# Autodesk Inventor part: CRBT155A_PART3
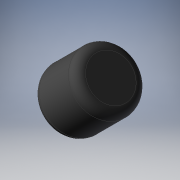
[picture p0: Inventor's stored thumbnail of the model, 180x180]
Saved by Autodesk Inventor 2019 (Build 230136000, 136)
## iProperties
Created: 2023-09
Part Number: CRBT155A_PART3
Material: Generic
Catalog Web Link: www.cadenas.de
Description: -
Vendor: IKO
Document SubType Name: Modeling
Designer: psAdmin
Manufacturer: IKO
Mass: 0.00605674 g
Surface Area: 0.171514 cm^2
Volume: 0.00605674 cm^3
Density: 1 g/cm^3
Appearance: PSOLRGB-192-192-192
Category: PARTsolutions
Company: IKO
Title: CRBT155A_PART3
Author: Cadenas PARTsolutions
PSOL_IDENT_0: {$CADENAS_DATA/23d-libs/iko/iko_bearings/crossed_rb/ultra_slim_type_crb/ultra_slim_type_crbt.prj},23
PSOL_IDENT_1: 2 {VTYP=3D},{NB=CRBT155A_PART3},{LINA=CRBT155A_PART3},{NN=Ultra Slim Type Crossed Roller Bearings (C
PSOL_IDENT_2: RBT...A)_PART3},{NOPRJ=TRUE},{DATE=09.07.2020 23:28:49},{GEOMDATE=08.07.2020 06:24:28},{VERSION=},{L
PSOL_IDENT_3: INEID=220},{WBVAR=},{WBNUMERIC=}  {NB=CRBT155A_PART3},{LINA=CRBT155A_PART3},{KT=DUMMY},{IDNR=},{STDR
PSOL_IDENT_4: T=15},{ORDER=CRBT155A},{MASS=11.9},{SD=15},{D=26},{B=5},{SR=0.15},{SDA=17.5},{DA=22.0},{DAR=2.0},{ZE
PSOL_IDENT_5: FF=16},{RS=0.3},{DETC=1.6},{PCDRL=19.6},{SDOR=20.10},{DIRR=19.10},{COG=0.0},{SDOG=0.0},{OH=0.0},{NH=
PSOL_IDENT_6: 0},{CR=1320},{COR=1110},{SC=0},{N=8},{N1=1.67}
NB: CRBT155A_PART3
NBSYN: $ORDER._PART3
LINA: CRBT155A_PART3
CATALOG: IKO (Nippon Thompson
STDRT: 15
ORDER: CRBT155A
MASS: 11.9
SD: 15
D: 26
B: 5
SR: 0.15
SDA: 17.5
DA: 22
CR: 1320
COR: 1110
SUPPLIER: IKO
ARTICLENO: CRBT155A_PART3
BOMINFO: CRBT155A_PART3
CREATOR: CADENAS GmbH
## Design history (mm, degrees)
sketch "Sketch_1"
  geometry: L1 (1.793, 9.093)-(3.207, 10.507); L2 (3.207, 10.507)-(3.702, 10.012); L3 (3.702, 9.588)-(2.712, 8.598); L4 (2.288, 8.598)-(1.793, 9.093); L5 (1.793, 9.093)-(3.207, 10.507); A1 r 0.3 centre (3.49, 9.8) between (3.702, 9.588) and (3.702, 10.012); A2 r 0.3 centre (2.5, 8.81) between (2.288, 8.598) and (2.712, 8.598)
  constraints: 10 end point, 4 point on circle, 2 centre point
revolve "Revolution1" sketch "Sketch_1" stored, may be unused: angle "d0" = 360 deg
body "Solid1"
